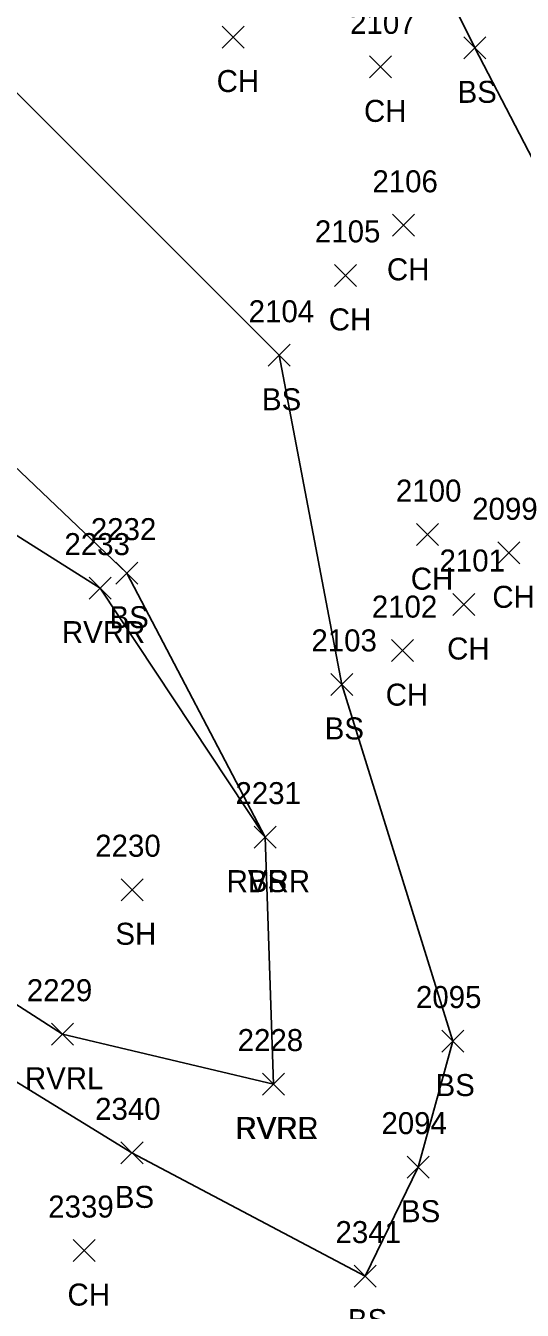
# Model space of a CAD drawing. Extents: x 1647133 to 1649138, y 411736 to 414924.
# Drawn here: x 1648953 to 1648998.1, y 412063.3 to 412180 of the extents above; entities that cross this region are included whole.
import ezdxf

# ---------------------------------------------------------------- set-up
doc = ezdxf.new("R2010")
doc.units = 0
for name, color, linetype in [('L_A', 7, 'Continuous'), ('L_I', 7, 'Continuous'), ('L_TIC', 7, 'Continuous'), ('LAWE', 7, 'Continuous'), ('LELB', 7, 'Continuous')]:
    doc.layers.add(name, color=color, linetype=linetype)

msp = doc.modelspace()

# ---------------------------------------------------------------- linework, layer by layer
at = {"layer": 'L_TIC'}
for points in [[(1648970.82, 412177.96), (1648972.82, 412179.96)], [(1648972.82, 412177.96), (1648970.82, 412179.96)], [(1648992.76, 412176.98), (1648994.76, 412178.98)], [(1648994.76, 412176.98), (1648992.76, 412178.98)], [(1648984.21, 412175.25), (1648986.21, 412177.25)], [(1648986.21, 412175.25), (1648984.21, 412177.25)], [(1648986.29, 412160.85), (1648988.29, 412162.85)], [(1648988.29, 412160.85), (1648986.29, 412162.85)], [(1648981.01, 412156.3), (1648983.01, 412158.3)], [(1648983.01, 412156.3), (1648981.01, 412158.3)], [(1648974.99, 412149.04), (1648976.99, 412151.04)], [(1648976.99, 412149.04), (1648974.99, 412151.04)], [(1648988.46, 412132.74), (1648990.46, 412134.74)], [(1648990.46, 412132.74), (1648988.46, 412134.74)], [(1648995.87, 412131.09), (1648997.87, 412133.09)], [(1648997.87, 412131.09), (1648995.87, 412133.09)], [(1648961.14, 412129.24), (1648963.14, 412131.24)], [(1648963.14, 412129.24), (1648961.14, 412131.24)], [(1648958.74, 412127.88), (1648960.74, 412129.88)], [(1648960.74, 412127.88), (1648958.74, 412129.88)], [(1648991.76, 412126.39), (1648993.76, 412128.39)], [(1648993.76, 412126.39), (1648991.76, 412128.39)], [(1648986.19, 412122.2), (1648988.19, 412124.2)], [(1648988.19, 412122.2), (1648986.19, 412124.2)], [(1648980.69, 412119.13), (1648982.69, 412121.13)], [(1648982.69, 412119.13), (1648980.69, 412121.13)], [(1648973.71, 412105.25), (1648975.71, 412107.25)], [(1648975.71, 412105.25), (1648973.71, 412107.25)], [(1648973.71, 412105.25), (1648975.71, 412107.25)], [(1648975.71, 412105.25), (1648973.71, 412107.25)], [(1648961.63, 412100.47), (1648963.63, 412102.47)], [(1648963.63, 412100.47), (1648961.63, 412102.47)], [(1648955.32, 412087.34), (1648957.32, 412089.34)], [(1648957.32, 412087.34), (1648955.32, 412089.34)], [(1648990.76, 412086.72), (1648992.76, 412088.72)], [(1648992.76, 412086.72), (1648990.76, 412088.72)], [(1648974.48, 412082.81), (1648976.48, 412084.81)], [(1648976.48, 412082.81), (1648974.48, 412084.81)], [(1648974.48, 412082.81), (1648976.48, 412084.81)], [(1648976.48, 412082.81), (1648974.48, 412084.81)], [(1648961.62, 412076.56), (1648963.62, 412078.56)], [(1648963.62, 412076.56), (1648961.62, 412078.56)], [(1648987.62, 412075.26), (1648989.62, 412077.26)], [(1648989.62, 412075.26), (1648987.62, 412077.26)], [(1648957.27, 412067.68), (1648959.27, 412069.68)], [(1648959.27, 412067.68), (1648957.27, 412069.68)], [(1648982.8, 412065.36), (1648984.8, 412067.36)], [(1648984.8, 412065.36), (1648982.8, 412067.36)]]:
    msp.add_lwpolyline(points, dxfattribs=at)
at = {"layer": 'LAWE'}
for points in [[(1648975.48, 412083.81), (1648974.71, 412106.25), (1648959.74, 412128.88), (1648928.28, 412148.71)], [(1648975.48, 412083.81), (1648956.32, 412088.34), (1648932.32, 412103.75), (1648924.99, 412117.88), (1648915.84, 412134.67), (1648909.22, 412137.09)]]:
    msp.add_lwpolyline(points, dxfattribs=at)
at = {"layer": 'LELB'}
for points in [[(1648910.34, 412307.48), (1648923.4, 412285.73), (1648930.01, 412277.07), (1648939.66, 412266.79), (1648945.95, 412259.16), (1648943.1, 412258.5), (1648935.16, 412254.46), (1648928.5, 412254.28), (1648924.41, 412254.2), (1648925.5, 412246.05), (1648929.64, 412242.7), (1648937.31, 412237.26), (1648939.74, 412232.88), (1648942.09, 412231.58), (1648961.5, 412231.41), (1648963.58, 412219.2), (1648985.51, 412194.57), (1648993.76, 412177.98), (1649005.16, 412156.05), (1649014.95, 412138.53), (1649020.66, 412120.02), (1649027.35, 412106.95), (1649037.64, 412094.49)], [(1648988.62, 412076.26), (1648991.76, 412087.72), (1648981.69, 412120.13), (1648975.99, 412150.04), (1648943.88, 412182.13), (1648927.94, 412194.05), (1648916.82, 412208.9), (1648904.26, 412218.44), (1648897.39, 412214.01), (1648892.18, 412224.47), (1648890.03, 412246.18), (1648887.99, 412265.68), (1648880.68, 412274.11), (1648875.37, 412283.75)], [(1648974.71, 412106.25), (1648962.14, 412130.24), (1648924.84, 412165.77), (1648916.54, 412176.78), (1648904.43, 412188.51), (1648892.09, 412182.61), (1648887.59, 412174.51), (1648883, 412162.55)], [(1648905.54, 412134.55), (1648909.56, 412132.74), (1648917.11, 412115.15), (1648917.83, 412101.46), (1648934.19, 412092.01), (1648947.54, 412086.81), (1648962.62, 412077.56), (1648983.8, 412066.36)], [(1648983.8, 412066.36), (1648988.62, 412076.26)]]:
    msp.add_lwpolyline(points, dxfattribs=at)

# ---------------------------------------------------------------- texts
at = {"layer": 'L_A'}
for s, p in [('CH', (1648970.31, 412173.96)), ('BS', (1648992.2, 412172.98)), ('CH', (1648983.7, 412171.25)), ('CH', (1648985.78, 412156.85)), ('CH', (1648980.5, 412152.3)), ('BS', (1648974.43, 412145.04)), ('CH', (1648987.95, 412128.74)), ('CH', (1648995.36, 412127.09)), ('BS', (1648960.58, 412125.24)), ('RVRR', (1648956.25, 412123.88)), ('CH', (1648991.25, 412122.39)), ('CH', (1648985.67, 412118.2)), ('BS', (1648980.13, 412115.13)), ('RVRR', (1648971.22, 412101.25)), ('BS', (1648973.15, 412101.25)), ('SH', (1648961.11, 412096.47)), ('RVRL', (1648952.89, 412083.34)), ('BS', (1648990.2, 412082.72)), ('RVRR', (1648971.99, 412078.81)), ('RVRL', (1648972.05, 412078.81)), ('BS', (1648961.06, 412072.56)), ('BS', (1648987.06, 412071.26)), ('CH', (1648956.76, 412063.68)), ('BS', (1648982.24, 412061.36))]:
    msp.add_text(s, height=2, dxfattribs=at).set_placement(p)
at = {"layer": 'L_I'}
for s, p in [('2107', (1648982.44, 412179.25)), ('2106', (1648984.46, 412164.85)), ('2105', (1648979.24, 412160.3)), ('2104', (1648973.22, 412153.04)), ('2100', (1648986.6, 412136.74)), ('2099', (1648993.53, 412135.09)), ('2232', (1648958.88, 412133.24)), ('2233', (1648956.48, 412131.88)), ('2101', (1648990.56, 412130.39)), ('2102', (1648984.41, 412126.2)), ('2103', (1648978.92, 412123.13)), ('2231', (1648972.02, 412109.25)), ('2231', (1648972.02, 412109.25)), ('2230', (1648959.28, 412104.47)), ('2229', (1648953.06, 412091.34)), ('2095', (1648988.42, 412090.72)), ('2228', (1648972.22, 412086.81)), ('2228', (1648972.22, 412086.81)), ('2340', (1648959.27, 412080.56)), ('2094', (1648985.28, 412079.26)), ('2339', (1648955.01, 412071.68)), ('2341', (1648981.11, 412069.36))]:
    msp.add_text(s, height=2, dxfattribs=at).set_placement(p)

doc.saveas('drawing.dxf')
